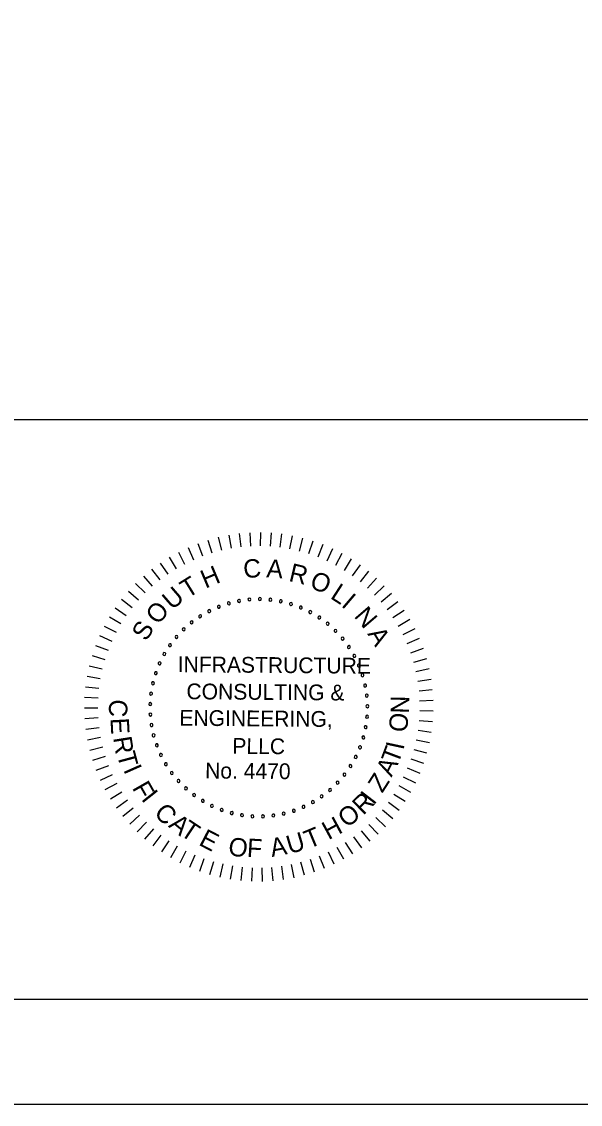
# Model space of a CAD drawing. Extents: x 96 to 240, y 601 to 689.
# Drawn here: x 196.67 to 207.27, y 601 to 621.55 of the extents above; entities that cross this region are included whole.
import ezdxf

# ---------------------------------------------------------------- set-up
doc = ezdxf.new("R2010")
doc.units = 0
for name, color, linetype in [('BR_BORDER LINES', 7, 'Continuous'), ('BR_TEXT', 7, 'Continuous'), ('Level 31', 7, 'Continuous')]:
    doc.layers.add(name, color=color, linetype=linetype)

msp = doc.modelspace()

# ---------------------------------------------------------------- linework, layer by layer
at = {"layer": 'BR_BORDER LINES'}
for p, q in [((186.375, 614.004), (207.836, 614.004)), ((103.173, 603.003), (237.837, 603.003))]:
    msp.add_line(p, q, dxfattribs=at)
at = {"layer": 'BR_TEXT'}
for p, q in [((200.401, 611.767), (200.46, 611.519)), ((200.599, 611.808), (200.643, 611.557)), ((200.798, 611.836), (200.827, 611.583)), ((201, 611.853), (201.013, 611.599)), ((201.202, 611.857), (201.199, 611.602)), ((201.403, 611.849), (201.386, 611.595)), ((201.604, 611.829), (201.571, 611.576)), ((201.804, 611.796), (201.755, 611.546)), ((202, 611.752), (201.937, 611.505)), ((199.828, 611.573), (199.931, 611.34)), ((200.015, 611.649), (200.104, 611.411)), ((200.206, 611.714), (200.28, 611.47)), ((202.194, 611.695), (202.116, 611.453)), ((202.384, 611.627), (202.291, 611.39)), ((202.57, 611.547), (202.463, 611.316)), ((199.469, 611.387), (199.6, 611.169)), ((199.646, 611.485), (199.763, 611.259)), ((202.75, 611.456), (202.629, 611.232)), ((202.925, 611.354), (202.79, 611.138)), ((199.136, 611.159), (199.293, 610.958)), ((199.299, 611.278), (199.443, 611.068)), ((203.093, 611.242), (202.945, 611.035)), ((203.253, 611.12), (203.093, 610.922)), ((198.981, 611.03), (199.149, 610.839)), ((203.406, 610.988), (203.235, 610.8)), ((198.695, 610.745), (198.885, 610.576)), ((198.833, 610.892), (199.013, 610.712)), ((203.551, 610.847), (203.368, 610.67)), ((198.565, 610.59), (198.766, 610.433)), ((203.687, 610.698), (203.493, 610.532)), ((203.813, 610.54), (203.61, 610.387)), ((198.446, 610.428), (198.655, 610.283)), ((203.93, 610.376), (203.718, 610.235)), ((198.336, 610.258), (198.554, 610.127)), ((204.036, 610.204), (203.816, 610.076)), ((198.149, 609.9), (198.381, 609.796)), ((198.237, 610.082), (198.463, 609.964)), ((204.132, 610.026), (203.904, 609.912)), ((198.072, 609.714), (198.31, 609.624)), ((204.217, 609.843), (203.982, 609.743)), ((198.007, 609.522), (198.25, 609.448)), ((204.29, 609.655), (204.05, 609.569)), ((197.953, 609.328), (198.2, 609.268)), ((204.352, 609.462), (204.107, 609.392)), ((197.911, 609.13), (198.162, 609.086)), ((204.402, 609.267), (204.153, 609.211)), ((204.44, 609.068), (204.188, 609.028)), ((197.882, 608.93), (198.135, 608.901)), ((204.465, 608.868), (204.212, 608.843)), ((197.864, 608.729), (198.119, 608.716)), ((204.479, 608.667), (204.224, 608.657)), ((197.859, 608.527), (198.114, 608.529)), ((204.48, 608.465), (204.225, 608.471)), ((197.867, 608.326), (198.121, 608.343)), ((204.469, 608.263), (204.215, 608.284)), ((197.886, 608.125), (198.139, 608.157)), ((204.445, 608.062), (204.193, 608.099)), ((197.918, 607.925), (198.168, 607.973)), ((204.41, 607.864), (204.161, 607.916)), ((197.962, 607.728), (198.209, 607.791)), ((204.362, 607.667), (204.117, 607.735)), ((198.018, 607.534), (198.26, 607.612)), ((198.086, 607.344), (198.323, 607.437)), ((204.303, 607.474), (204.062, 607.557)), ((198.165, 607.158), (198.396, 607.265)), ((204.231, 607.285), (203.996, 607.382)), ((198.255, 606.977), (198.479, 607.098)), ((204.055, 606.922), (203.833, 607.047)), ((204.149, 607.101), (203.92, 607.212)), ((198.356, 606.802), (198.572, 606.937)), ((203.951, 606.749), (203.737, 606.887)), ((198.468, 606.634), (198.675, 606.782)), ((198.589, 606.473), (198.787, 606.633)), ((203.836, 606.583), (203.631, 606.734)), ((198.72, 606.319), (198.909, 606.491)), ((203.577, 606.273), (203.392, 606.448)), ((203.712, 606.424), (203.516, 606.587)), ((198.861, 606.174), (199.038, 606.357)), ((199.01, 606.038), (199.176, 606.231)), ((203.283, 605.997), (203.12, 606.193)), ((203.434, 606.131), (203.26, 606.316)), ((199.167, 605.911), (199.32, 606.114)), ((199.331, 605.794), (199.472, 606.005)), ((203.124, 605.873), (202.973, 606.079)), ((199.502, 605.687), (199.63, 605.907)), ((199.68, 605.59), (199.794, 605.818)), ((202.604, 605.562), (202.494, 605.792)), ((202.784, 605.655), (202.659, 605.878)), ((202.957, 605.759), (202.819, 605.973)), ((199.863, 605.505), (199.963, 605.739)), ((200.051, 605.431), (200.136, 605.671)), ((200.243, 605.368), (200.314, 605.613)), ((202.037, 605.351), (201.97, 605.597)), ((202.231, 605.41), (202.149, 605.651)), ((202.42, 605.481), (202.323, 605.716)), ((200.438, 605.318), (200.494, 605.566)), ((200.636, 605.279), (200.677, 605.53)), ((200.836, 605.253), (200.862, 605.506)), ((201.038, 605.238), (201.048, 605.493)), ((201.24, 605.236), (201.234, 605.491)), ((201.441, 605.247), (201.42, 605.501)), ((201.642, 605.269), (201.606, 605.522)), ((201.841, 605.304), (201.789, 605.554))]:
    msp.add_line(p, q, dxfattribs=at)
for centre, start, end in [((200.601, 610.512), 16.1422, 196.1422), ((200.601, 610.512), 196.1422, 16.1422), ((200.795, 610.558), 10.6038, 190.6038), ((200.795, 610.558), 190.6038, 10.6038), ((200.993, 610.585), 5.0653, 185.0653), ((200.993, 610.585), 185.0653, 5.0653), ((201.192, 610.593), 359.5268, 179.5268), ((201.192, 610.593), 179.5268, 359.5268), ((201.391, 610.581), 353.9884, 173.9884), ((201.391, 610.581), 173.9884, 353.9884), ((201.588, 610.55), 348.4499, 168.4499), ((201.588, 610.55), 168.4499, 348.4499), ((201.781, 610.5), 162.9114, 342.9114), ((201.781, 610.5), 342.9114, 162.9114), ((200.231, 610.366), 27.2191, 207.2191), ((200.231, 610.366), 207.2191, 27.2191), ((200.412, 610.448), 21.6807, 201.6807), ((200.412, 610.448), 201.6807, 21.6807), ((201.968, 610.432), 157.373, 337.373), ((201.968, 610.432), 337.373, 157.373), ((202.148, 610.346), 151.8345, 331.8345), ((202.148, 610.346), 331.8345, 151.8345), ((199.896, 610.151), 38.2961, 218.2961), ((199.896, 610.151), 218.2961, 38.2961), ((200.058, 610.267), 32.7576, 212.7576), ((200.058, 610.267), 212.7576, 32.7576), ((202.319, 610.244), 146.2961, 326.2961), ((202.319, 610.244), 326.2961, 146.2961), ((202.479, 610.125), 140.7576, 320.7576), ((202.479, 610.125), 320.7576, 140.7576), ((199.608, 609.876), 49.373, 229.373), ((199.608, 609.876), 229.373, 49.373), ((199.745, 610.021), 43.8345, 223.8345), ((199.745, 610.021), 223.8345, 43.8345), ((202.627, 609.991), 135.2191, 315.2191), ((202.627, 609.991), 315.2191, 135.2191), ((199.485, 609.719), 54.9114, 234.9114), ((199.485, 609.719), 234.9114, 54.9114), ((202.761, 609.844), 129.6807, 309.6807), ((202.761, 609.844), 309.6807, 129.6807), ((202.88, 609.684), 124.1422, 304.1422), ((202.88, 609.684), 304.1422, 124.1422), ((199.378, 609.551), 60.4499, 240.4499), ((199.378, 609.551), 240.4499, 60.4499), ((202.984, 609.514), 118.6038, 298.6038), ((202.984, 609.514), 298.6038, 118.6038), ((199.288, 609.373), 65.9884, 245.9884), ((199.288, 609.373), 245.9884, 65.9884), ((203.07, 609.334), 113.0653, 293.0653), ((203.07, 609.334), 293.0653, 113.0653), ((199.216, 609.187), 71.5268, 251.5268), ((199.216, 609.187), 251.5268, 71.5268), ((203.139, 609.147), 107.5268, 287.5268), ((203.139, 609.147), 287.5268, 107.5268), ((199.161, 608.996), 77.0653, 257.0653), ((199.161, 608.996), 257.0653, 77.0653), ((203.189, 608.954), 101.9884, 281.9884), ((203.189, 608.954), 281.9884, 101.9884), ((199.126, 608.799), 82.6038, 262.6038), ((199.126, 608.799), 262.6038, 82.6038), ((203.221, 608.758), 96.4499, 276.4499), ((203.221, 608.758), 276.4499, 96.4499), ((199.109, 608.601), 88.1422, 268.1422), ((199.109, 608.601), 268.1422, 88.1422), ((203.233, 608.559), 90.9114, 270.9114), ((203.233, 608.559), 270.9114, 90.9114), ((199.112, 608.402), 93.6807, 273.6807), ((199.112, 608.402), 273.6807, 93.6807), ((203.226, 608.359), 85.373, 265.373), ((203.226, 608.359), 265.373, 85.373), ((199.134, 608.203), 99.2191, 279.2191), ((199.134, 608.203), 279.2191, 99.2191), ((199.175, 608.008), 284.7576, 104.7576), ((203.2, 608.162), 79.8345, 259.8345), ((203.2, 608.162), 259.8345, 79.8345), ((199.175, 608.008), 104.7576, 284.7576), ((199.235, 607.818), 110.2961, 290.2961), ((199.235, 607.818), 290.2961, 110.2961), ((203.155, 607.968), 74.2961, 254.2961), ((203.155, 607.968), 254.2961, 74.2961), ((199.312, 607.635), 115.8345, 295.8345), ((199.312, 607.635), 295.8345, 115.8345), ((203.092, 607.779), 68.7576, 248.7576), ((203.092, 607.779), 248.7576, 68.7576), ((199.407, 607.459), 121.373, 301.373), ((199.407, 607.459), 301.373, 121.373), ((202.912, 607.424), 57.6807, 237.6807), ((202.912, 607.424), 237.6807, 57.6807), ((203.01, 607.597), 63.2191, 243.2191), ((203.01, 607.597), 243.2191, 63.2191), ((199.519, 607.294), 126.9114, 306.9114), ((199.519, 607.294), 306.9114, 126.9114), ((202.797, 607.261), 52.1422, 232.1422), ((202.797, 607.261), 232.1422, 52.1422), ((199.646, 607.141), 132.4499, 312.4499), ((199.646, 607.141), 312.4499, 132.4499), ((199.787, 607), 137.9884, 317.9884), ((199.787, 607), 317.9884, 137.9884), ((202.667, 607.11), 46.6038, 226.6038), ((202.667, 607.11), 226.6038, 46.6038), ((199.941, 606.874), 143.5268, 323.5268), ((199.941, 606.874), 323.5268, 143.5268), ((202.366, 606.849), 35.5268, 215.5268), ((202.366, 606.849), 215.5268, 35.5268), ((202.523, 606.972), 41.0653, 221.0653), ((202.523, 606.972), 221.0653, 41.0653), ((200.107, 606.763), 149.0653, 329.0653), ((200.107, 606.763), 329.0653, 149.0653), ((200.282, 606.668), 154.6038, 334.6038), ((200.282, 606.668), 334.6038, 154.6038), ((200.466, 606.591), 160.1422, 340.1422), ((200.466, 606.591), 340.1422, 160.1422), ((201.835, 606.577), 18.9114, 198.9114), ((202.021, 606.65), 24.4499, 204.4499), ((202.021, 606.65), 204.4499, 24.4499), ((202.198, 606.741), 29.9884, 209.9884), ((202.198, 606.741), 209.9884, 29.9884), ((200.657, 606.532), 345.6807, 165.6807), ((200.657, 606.532), 165.6807, 345.6807), ((200.852, 606.492), 351.2191, 171.2191), ((200.852, 606.492), 171.2191, 351.2191), ((201.05, 606.471), 356.7576, 176.7576), ((201.05, 606.471), 176.7576, 356.7576), ((201.249, 606.469), 2.2961, 182.2961), ((201.249, 606.469), 182.2961, 2.2961), ((201.448, 606.486), 7.8345, 187.8345), ((201.448, 606.486), 187.8345, 7.8345), ((201.644, 606.522), 13.373, 193.373), ((201.644, 606.522), 193.373, 13.373), ((201.835, 606.577), 198.9114, 18.9114)]:
    msp.add_arc(centre, 0.028, start, end, dxfattribs=at)
at = {"layer": 'Level 31'}
msp.add_lwpolyline([(95.84, 689.004), (95.84, 601.004), (239.84, 601.004), (239.84, 689.004)], dxfattribs=at)

# ---------------------------------------------------------------- texts
at = {"layer": 'BR_TEXT'}
for s, height, rotation, p in [('C', 0.349, 4.7281, (200.89, 610.987)), ('A', 0.349, 355.6981, (201.308, 611.007)), ('H', 0.349, 22.7882, (200.158, 610.789)), ('R', 0.349, 346.6681, (201.725, 610.939)), ('T', 0.349, 31.8182, (199.819, 610.599)), ('O', 0.349, 337.638, (202.116, 610.819)), ('U', 0.349, 40.8482, (199.526, 610.374)), ('L', 0.349, 327.108, (202.511, 610.618)), ('O', 0.349, 49.8782, (199.258, 610.09)), ('I', 0.349, 319.578, (202.721, 610.466)), ('N', 0.349, 310.548, (202.965, 610.263)), ('S', 0.349, 58.9083, (199.036, 609.777)), ('A', 0.349, 301.5179, (203.225, 609.934)), ('INFRASTRUCTURE', 0.29909, 359.5268, (199.631, 609.207)), ('CONSULTING &', 0.29909, 359.5268, (199.796, 608.693)), ('C', 0.349, 267.025, (198.336, 608.698)), ('N', 0.349, 89.2085, (204.022, 608.419)), ('ENGINEERING,', 0.29909, 359.5268, (199.662, 608.191)), ('E', 0.349, 273.025, (198.354, 608.331)), ('O', 0.349, 83.2085, (203.978, 608.053)), ('R', 0.349, 279.025, (198.405, 607.962)), ('PLLC', 0.2991, 359.5268, (200.668, 607.657)), ('I', 0.349, 77.9093, (203.916, 607.716)), ('T', 0.349, 285.025, (198.475, 607.647)), ('T', 0.349, 69.3954, (203.813, 607.446)), ('I', 0.349, 293.7713, (198.593, 607.355)), ('No. 4470', 0.2991, 359.5268, (200.15, 607.189)), ('A', 0.349, 63.3954, (203.69, 607.204)), ('Z', 0.349, 57.3954, (203.514, 606.899)), ('F', 0.349, 299.7713, (198.758, 607.01)), ('I', 0.349, 308.5268, (198.927, 606.795)), ('R', 0.349, 44.5268, (203.153, 606.479)), ('I', 0.349, 52.3339, (203.35, 606.668)), ('C', 0.349, 314.5268, (199.164, 606.515)), ('O', 0.349, 38.5268, (202.846, 606.239)), ('A', 0.349, 320.5268, (199.441, 606.28)), ('T', 0.349, 326.5268, (199.658, 606.126)), ('H', 0.349, 28.5268, (202.494, 606.015)), ('E', 0.349, 332.5268, (200.013, 605.935)), ('T', 0.349, 22.5268, (202.121, 605.848)), ('O', 0.349, 350.5268, (200.573, 605.74)), ('F', 0.349, 356.5268, (200.939, 605.703)), ('A', 0.349, 10.5268, (201.419, 605.697)), ('U', 0.349, 16.5268, (201.754, 605.751))]:
    msp.add_text(s, height=height, rotation=rotation, dxfattribs=at).set_placement(p)

doc.saveas('drawing.dxf')
